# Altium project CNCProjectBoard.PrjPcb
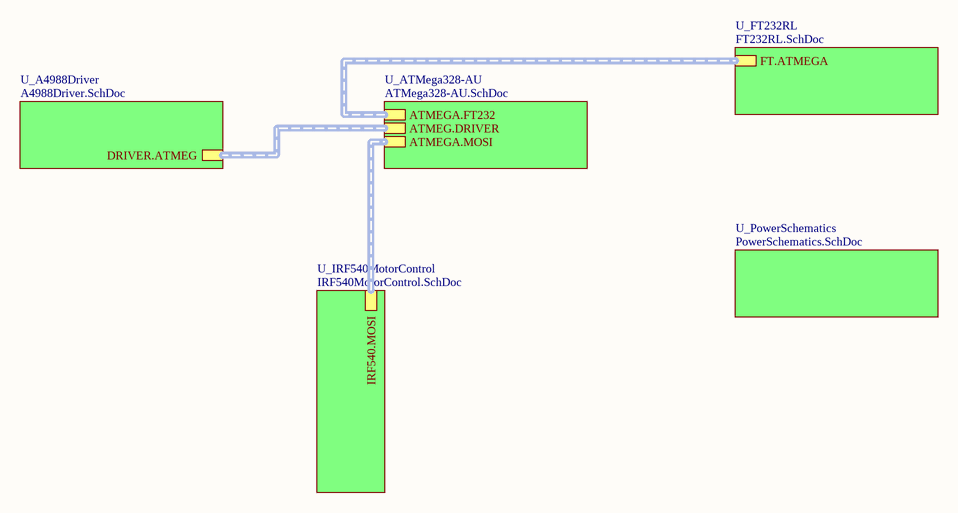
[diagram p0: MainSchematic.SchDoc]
6 sheets, 89 parts. Net scope: hierarchical (ports join the sheet entries above them; power ports are global).
Board file: PCB1.PcbDoc
Sheets:
  MainSchematic.SchDoc
    U_A4988Driver = A4988Driver.SchDoc
    U_ATMega328-AU = ATMega328-AU.SchDoc
    U_FT232RL = FT232RL.SchDoc
    U_IRF540MotorControl = IRF540MotorControl.SchDoc
    U_PowerSchematics = PowerSchematics.SchDoc

## Sheet MainSchematic.SchDoc
size A; SheetNumber: 1; SheetTotal: 6

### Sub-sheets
U_A4988Driver = A4988Driver.SchDoc: DRIVER.ATMEG (harness DRIVER-ATMEGA)
U_ATMega328-AU = ATMega328-AU.SchDoc: ATMEGA.FT232 (harness FT-ATMega), ATMEG.DRIVER (harness DRIVER-ATMEGA), ATMEGA.MOSI (harness IRF540-ATMEGA)
U_FT232RL = FT232RL.SchDoc: FT.ATMEGA (harness FT-ATMega)
U_IRF540MotorControl = IRF540MotorControl.SchDoc: IRF540.MOSI (harness IRF540-ATMEGA)
U_PowerSchematics = PowerSchematics.SchDoc: no entries

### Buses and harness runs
harness sheet U_A4988Driver/DRIVER.ATMEG = sheet U_ATMega328-AU/ATMEG.DRIVER
harness sheet U_ATMega328-AU/ATMEGA.FT232 = sheet U_FT232RL/FT.ATMEGA
harness sheet U_ATMega328-AU/ATMEGA.MOSI = sheet U_IRF540MotorControl/IRF540.MOSI

## Sheet A4988Driver.SchDoc
size A4; SheetNumber: 2; SheetTotal: 6
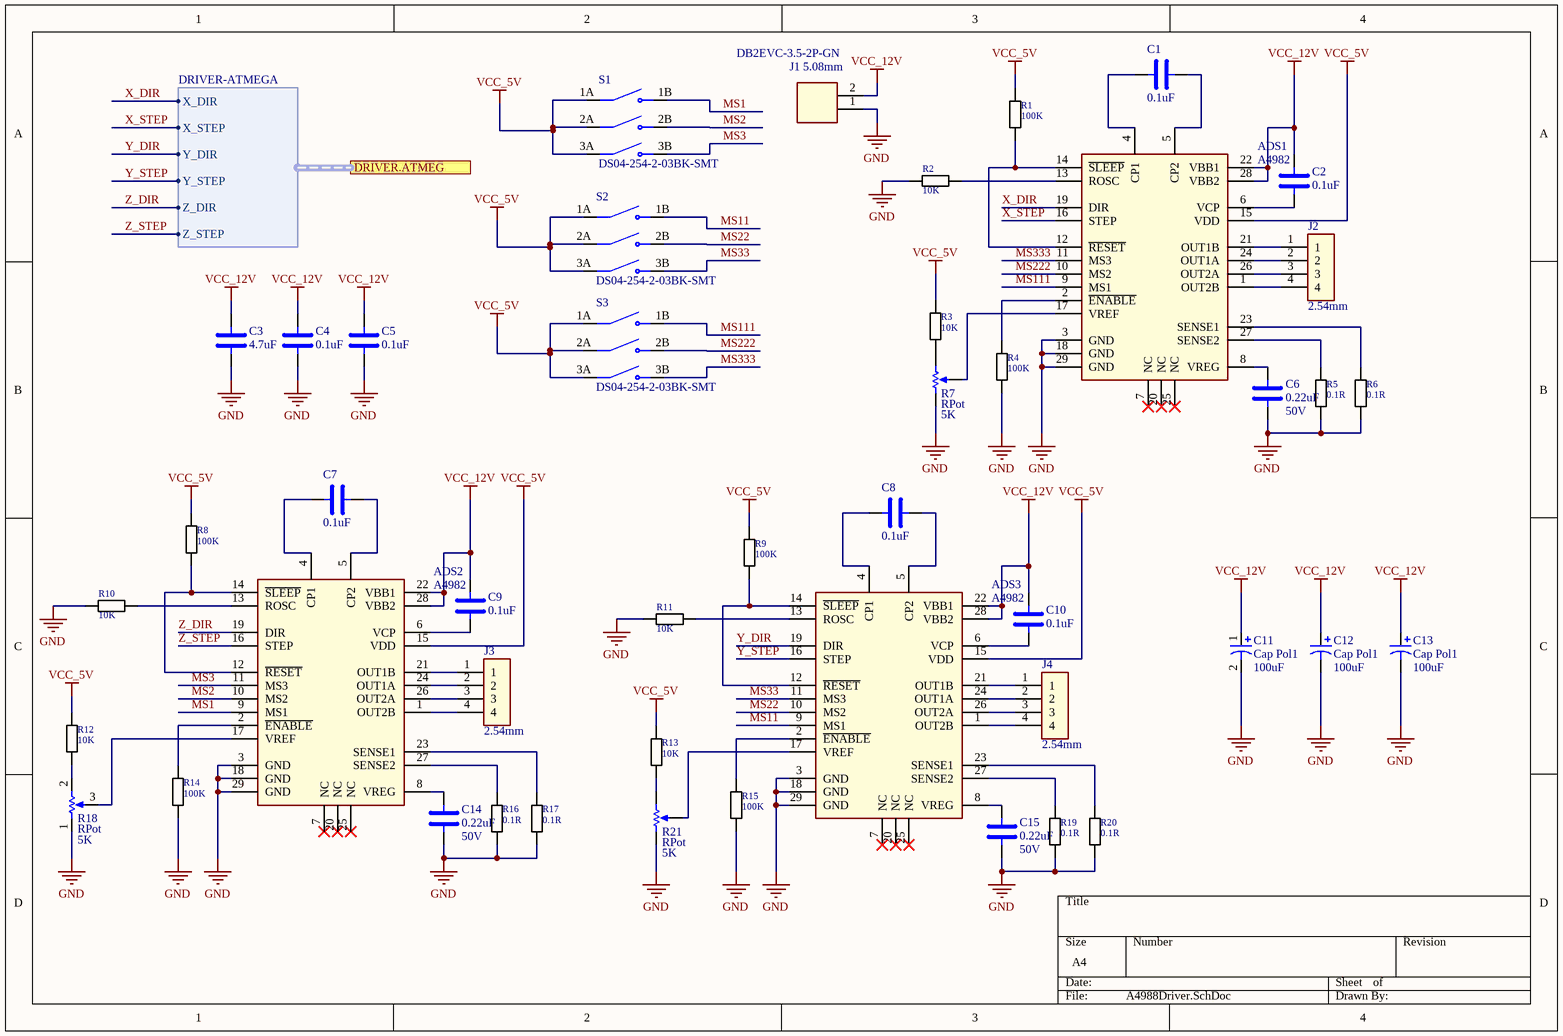
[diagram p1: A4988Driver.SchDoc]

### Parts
ADS1  A4982  [QFN50P500X500X90-29N]
ADS2  A4982  [QFN50P500X500X90-29N]
ADS3  A4982  [QFN50P500X500X90-29N]
C1  0.1uF  [CAPC2012X140N]
C2  0.1uF  [CAPC2012X140N]
C3  4.7uF  [CAPC2012X140N]
C4  0.1uF  [CAPC2012X140N]
C5  0.1uF  [CAPC2012X140N]
C6  0.22uF  Voltage: 50V  [CAPC2012X140N]
C7  0.1uF  [CAPC2012X140N]
C8  0.1uF  [CAPC2012X140N]
C9  0.1uF  [CAPC2012X140N]
C10  0.1uF  [CAPC2012X140N]
C11  Cap Pol1  value 100uF  [CAPPRD250W50D630H1500]
C12  Cap Pol1  value 100uF  [CAPPRD250W50D630H1500]
C13  Cap Pol1  value 100uF  [CAPPRD250W50D630H1500]
C14  0.22uF  Voltage: 50V  [CAPC2012X140N]
C15  0.22uF  Voltage: 50V  [CAPC2012X140N]
J1  DB2EVC-3.5-2P-GN  Pitch: 5.08mm  [5MM_2POS_TERM_BLOCK]
J2  2.54mm  [HEADER1X4]
J3  2.54mm  [HEADER1X4]
J4  2.54mm  [HEADER1X4]
R1  100K  [RESC2012X60N]
R2  10K  [RESC2012X60N]
R3  10K  [RESC2012X60N]
R4  100K  [RESC2012X60N]
R5  0.1R  [RESAD1100W55L680D260]
R6  0.1R  [RESAD1100W55L680D260]
R7  RPot  value 5K  [PT10RV10103A2020PMS]
R8  100K  [RESC2012X60N]
R9  100K  [RESC2012X60N]
R10  10K  [RESC2012X60N]
R11  10K  [RESC2012X60N]
R12  10K  [RESC2012X60N]
R13  10K  [RESC2012X60N]
R14  100K  [RESC2012X60N]
R15  100K  [RESC2012X60N]
R16  0.1R  [RESAD1100W55L680D260]
R17  0.1R  [RESAD1100W55L680D260]
R18  RPot  value 5K  [PT10RV10103A2020PMS]
R19  0.1R  [RESAD1100W55L680D260]
R20  0.1R  [RESAD1100W55L680D260]
R21  RPot  value 5K  [PT10RV10103A2020PMS]
S1  DS04-254-2-03BK-SMT  [SW_DS01-254-S-03BE]
S2  DS04-254-2-03BK-SMT  [SW_DS01-254-S-03BE]
S3  DS04-254-2-03BK-SMT  [SW_DS01-254-S-03BE]

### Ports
DRIVER.ATMEG (harness DRIVER-ATMEGA)

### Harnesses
DRIVER-ATMEGA: X_DIR, X_STEP, Y_DIR, Y_STEP, Z_DIR, Z_STEP

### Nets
GND: ADS1.3(GND) ADS1.18(GND) ADS1.29(GND) ADS2.3(GND) ADS2.18(GND) ADS2.29(GND) ADS3.3(GND) ADS3.18(GND) ADS3.29(GND) C3.1 C4.1 C5.1 C6.1 C11.2 C12.2 C13.2 C14.1 C15.1 J1.1 R2.1 R4.1 R5.1 R6.1 R7.1(TOP) R10.1 R11.1 R14.1 R15.1 R16.1 R17.1 R18.1(TOP) R19.1 R20.1 R21.1(TOP)
VCC_5V: ADS1.15(VDD) ADS2.15(VDD) ADS3.15(VDD) R1.2 R3.2 R8.2 R9.2 R12.2 R13.2 S1.1A(COM1) S1.2A(COM2) S1.3A(COM3) S2.1A(COM1) S2.2A(COM2) S2.3A(COM3) S3.1A(COM1) S3.2A(COM2) S3.3A(COM3)
VCC_12V: ADS1.22(VBB1) ADS1.28(VBB2) ADS2.22(VBB1) ADS2.28(VBB2) ADS3.22(VBB1) ADS3.28(VBB2) C2.2 C3.2 C4.2 C5.2 C9.2 C10.2 C11.1 C12.1 C13.1 J1.2
MS1: ADS2.9(MS1) S1.1B(NO1)
MS2: ADS2.10(MS2) S1.2B(NO2)
MS3: ADS2.11(MS3) S1.3B(NO3)
MS11: ADS3.9(MS1) S2.1B(NO1)
MS22: ADS3.10(MS2) S2.2B(NO2)
MS33: ADS3.11(MS3) S2.3B(NO3)
MS111: ADS1.9(MS1) S3.1B(NO1)
MS222: ADS1.10(MS2) S3.2B(NO2)
MS333: ADS1.11(MS3) S3.3B(NO3)
X_DIR: ADS1.19(DIR) ; port DRIVER.ATMEG.X_DIR
X_STEP: ADS1.16(STEP) ; port DRIVER.ATMEG.X_STEP
Y_DIR: ADS3.19(DIR) ; port DRIVER.ATMEG.Y_DIR
Y_STEP: ADS3.16(STEP) ; port DRIVER.ATMEG.Y_STEP
Z_DIR: ADS2.19(DIR) ; port DRIVER.ATMEG.Z_DIR
Z_STEP: ADS2.16(STEP) ; port DRIVER.ATMEG.Z_STEP
NetADS1_1: ADS1.1(OUT2B) J2.4
NetADS1_2: ADS1.2(~{ENABLE}) R4.2
NetADS1_4: ADS1.4(CP1) C1.2
NetADS1_5: ADS1.5(CP2) C1.1
NetADS1_6: ADS1.6(VCP) C2.1
NetADS1_8: ADS1.8(VREG) C6.2
NetADS1_12: ADS1.12(~{RESET}) ADS1.14(~{SLEEP}) R1.1
NetADS1_13: ADS1.13(ROSC) R2.2
NetADS1_17: ADS1.17(VREF) R7.3(TAP)
NetADS1_21: ADS1.21(OUT1B) J2.1
NetADS1_23: ADS1.23(SENSE1) R6.2
NetADS1_24: ADS1.24(OUT1A) J2.2
NetADS1_26: ADS1.26(OUT2A) J2.3
NetADS1_27: ADS1.27(SENSE2) R5.2
NetADS2_1: ADS2.1(OUT2B) J3.4
NetADS2_2: ADS2.2(~{ENABLE}) R14.2
NetADS2_4: ADS2.4(CP1) C7.2
NetADS2_5: ADS2.5(CP2) C7.1
NetADS2_6: ADS2.6(VCP) C9.1
NetADS2_8: ADS2.8(VREG) C14.2
NetADS2_12: ADS2.12(~{RESET}) ADS2.14(~{SLEEP}) R8.1
NetADS2_13: ADS2.13(ROSC) R10.2
NetADS2_17: ADS2.17(VREF) R18.3(TAP)
NetADS2_21: ADS2.21(OUT1B) J3.1
NetADS2_23: ADS2.23(SENSE1) R17.2
NetADS2_24: ADS2.24(OUT1A) J3.2
NetADS2_26: ADS2.26(OUT2A) J3.3
NetADS2_27: ADS2.27(SENSE2) R16.2
NetADS3_1: ADS3.1(OUT2B) J4.4
NetADS3_2: ADS3.2(~{ENABLE}) R15.2
NetADS3_4: ADS3.4(CP1) C8.2
NetADS3_5: ADS3.5(CP2) C8.1
NetADS3_6: ADS3.6(VCP) C10.1
NetADS3_8: ADS3.8(VREG) C15.2
NetADS3_12: ADS3.12(~{RESET}) ADS3.14(~{SLEEP}) R9.1
NetADS3_13: ADS3.13(ROSC) R11.2
NetADS3_17: ADS3.17(VREF) R21.3(TAP)
NetADS3_21: ADS3.21(OUT1B) J4.1
NetADS3_23: ADS3.23(SENSE1) R20.2
NetADS3_24: ADS3.24(OUT1A) J4.2
NetADS3_26: ADS3.26(OUT2A) J4.3
NetADS3_27: ADS3.27(SENSE2) R19.2
NetR3_1: R3.1 R7.2(BOT)
NetR12_1: R12.1 R18.2(BOT)
NetR13_1: R13.1 R21.2(BOT)

Not connected (* = marked no-connect by the designer): ADS1 7(NC)* 20(NC)* 25(NC)*; ADS2 7(NC)* 20(NC)* 25(NC)*; ADS3 7(NC)* 20(NC)* 25(NC)*

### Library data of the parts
C1 C2 C4 C5 C7-C10 = CAP CER 0.1uF
C3 = CAP CER 4.7uF
C6 C14 C15 = CAP CER 0.22uF 0603 50VDC 10% X5R: Manufacturer: YAGEO; Manufacturer Part Number: CC0603JRNPO9BN180
C11-C13 = Cap Pol1: Polarized Capacitor (Radial)
J1 = TERM_BLOCK_2PIN_VERT_3.5MM: 300V 8A 2 Straight pin -40℃~+105℃ 1 3.5mm Green Board Edge/Receptacle-Close Plugin,P=3.5mm Pluggable System Terminal Block ROHS; Manufacturer: DIBO; Number of Positions: 2
J2-J4 = Header_1x4: Male Header 1x4; Manufacturer: Ckmtw(Shenzhen Cankemeng); Manufacturer Part Number: B-2100S04P-A110; Number of Positions: 4
R1 R4 R8 R9 R14 R15 = RES 100K 0603 100mW 0.1%: Manufacturer: YAGEO; Manufacturer Part Number: RT0603BRD07100KL
R2 R10 R11 = RES 10K 0603 100mW 0.1%: Manufacturer: YAGEO; Manufacturer Part Number: RT0603BRE0710KL
R3 R12 R13 = RES 10K 0805 125mW 1%: Manufacturer: UNI-ROYAL(Uniroyal Elec); Manufacturer Part Number: 0805W8F1002T5E
R5 R6 R16 R17 R19 R20 = RES 0.1R TH
R7 R18 R21 = RPot: Potentiometer; Sim Note: Enter the Resistance value and the set point into parameter fields.; Set Position: 0.5
S1-S3 = DS04-254-2-03BK-SMT: DS05-127-2-04BK-SMT-TR; MF: {'manufacturer': u'CUI'}

## Sheet ATMega328-AU.SchDoc
size A4; SheetNumber: 3; SheetTotal: 6
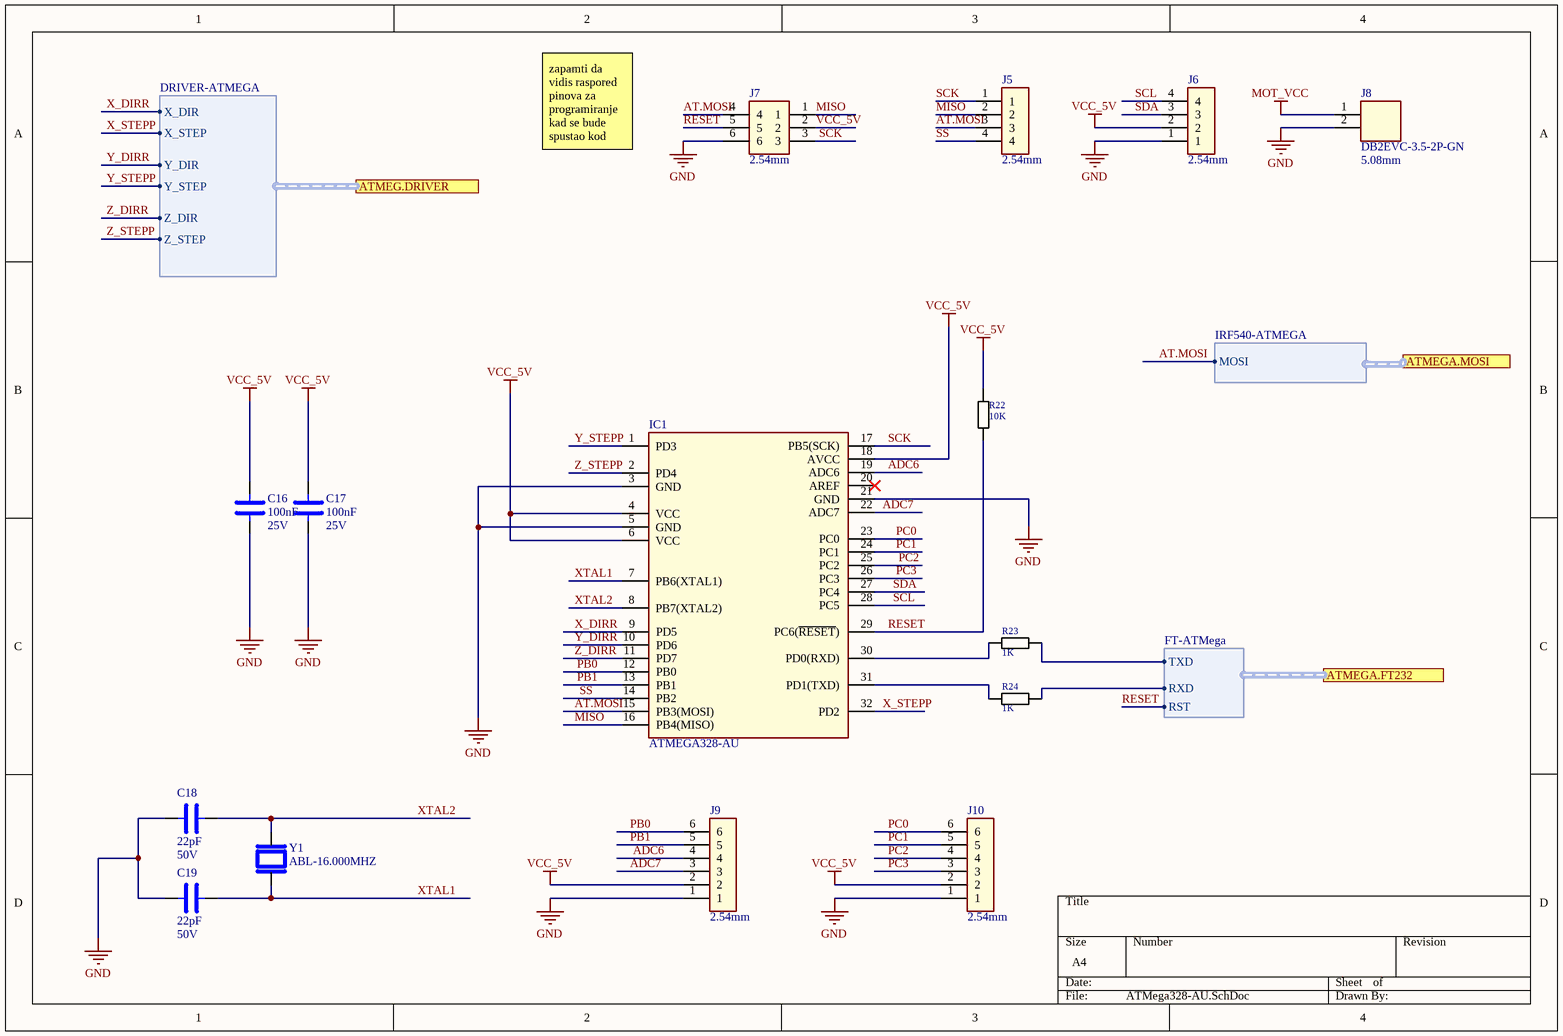
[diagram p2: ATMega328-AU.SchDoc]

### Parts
C16  100nF  Voltage: 25V  [CAPC2012X140N]
C17  100nF  Voltage: 25V  [CAPC2012X140N]
C18  22pF  Voltage: 50V  [CAPC2012X140N]
C19  22pF  Voltage: 50V  [CAPC2012X140N]
IC1  ATMEGA328-AU  [QFP80P900X900X120-32N]
J5  2.54mm  [HEADER1X4]
J6  2.54mm  [HEADER1X4]
J7  2.54mm  [TE_5-146257-3]
J8  DB2EVC-3.5-2P-GN  Pitch: 5.08mm  [5MM_2POS_TERM_BLOCK]
J9  2.54mm  [HEADER1X6]
J10  2.54mm  [HEADER1X6]
R22  10K  [RESC2012X60N]
R23  1K  [RESC2012X60N]
R24  1K  [RESC2012X60N]
Y1  ABL-16.000MHZ  [XTAL_ECS-30-S-1X]

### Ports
ATMEG.DRIVER (harness DRIVER-ATMEGA), ATMEGA.FT232 (harness FT-ATMega), ATMEGA.MOSI (harness IRF540-ATMEGA)

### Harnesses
FT-ATMega: TXD, RXD, RST
DRIVER-ATMEGA: X_DIR, Y_DIR, Z_STEP, X_STEP, Z_DIR, Y_STEP
IRF540-ATMEGA: MOSI

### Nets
GND: C16.1 C17.1 C18.2 C19.2 IC1.3(GND) IC1.5(GND) IC1.21(GND) J6.1 J7.6 J8.2 J9.1 J10.1
MOT_VCC: J8.1
VCC_5V: C16.2 C17.2 IC1.4(VCC) IC1.6(VCC) IC1.18(AVCC) J6.2 J7.2 J9.2 J10.2 R22.2
ADC6: IC1.19(ADC6) J9.4
ADC7: IC1.22(ADC7) J9.3
AT.MOSI: IC1.15(PB3(MOSI)) J5.3 J7.4 ; port ATMEGA.MOSI.MOSI
MISO: IC1.16(PB4(MISO)) J5.2 J7.1
PB0: IC1.12(PB0) J9.6
PB1: IC1.13(PB1) J9.5
PC0: IC1.23(PC0) J10.6
PC1: IC1.24(PC1) J10.5
PC2: IC1.25(PC2) J10.4
PC3: IC1.26(PC3) J10.3
RESET: IC1.29(PC6(~{RESET})) J7.5 R22.1 ; port ATMEGA.FT232.RST
RXD: R24.2 ; port ATMEGA.FT232.RXD
SCK: IC1.17(PB5(SCK)) J5.1 J7.3
SCL: IC1.28(PC5) J6.4
SDA: IC1.27(PC4) J6.3
SS: IC1.14(PB2) J5.4
TXD: R23.2 ; port ATMEGA.FT232.TXD
X_DIRR: IC1.9(PD5) ; port ATMEG.DRIVER.X_DIR  [project net X_DIR]
X_STEPP: IC1.32(PD2) ; port ATMEG.DRIVER.X_STEP  [project net X_STEP]
XTAL1: C19.1 IC1.7(PB6(XTAL1)) Y1.1
XTAL2: C18.1 IC1.8(PB7(XTAL2)) Y1.2
Y_DIRR: IC1.10(PD6) ; port ATMEG.DRIVER.Y_DIR  [project net Y_DIR]
Y_STEPP: IC1.1(PD3) ; port ATMEG.DRIVER.Y_STEP  [project net Y_STEP]
Z_DIRR: IC1.11(PD7) ; port ATMEG.DRIVER.Z_DIR  [project net Z_DIR]
Z_STEPP: IC1.2(PD4) ; port ATMEG.DRIVER.Z_STEP  [project net Z_STEP]
NetIC1_30: IC1.30(PD0(RXD)) R23.1
NetIC1_31: IC1.31(PD1(TXD)) R24.1

Not connected (* = marked no-connect by the designer): IC1 20(AREF)*

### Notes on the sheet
- zapamti da vidis raspored pinova za programiranje kad se bude spustao kod

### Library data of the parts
C16 C17 = CAP CER 100nF 0603 25VDC 10% X7R: Manufacturer: Samsung Electro-Mechanics; Manufacturer Part Number: CL10B104KA8NNNC
C18 C19 = CAP CER 22pF 0805 50VDC 10% X5R: Manufacturer: Samsung Electro-Mechanics; Manufacturer Part Number: CL10A106KP8NNNC
J5 J6 = Header_1x4: as J2 on sheet A4988Driver
J7 = Header_2x3: Male Header 2x3
J8 = TERM_BLOCK_2PIN_VERT_3.5MM: as J1 on sheet A4988Driver
J9 J10 = Header_1x6: Female Header 1x6; Manufacturer: MOLEX; Manufacturer Part Number: 0901471106; Number of Positions: 6
R22 = RES 10K 0603 100mW 0.1%: as R2 on sheet A4988Driver
R23 R24 = RES 1K 0603 250mW 5%: RES 100K 0603 250mW 5%; Manufacturer: Panasonic; Manufacturer Part Number: ERJ-PA3J102V
Y1 = ABL-16.000MHZ: 16 MHz Â±10ppm Crystal 18pF 40 Ohms HC-49/US; MF: Abracon Corporation

## Sheet FT232RL.SchDoc
size A4; SheetNumber: 5; SheetTotal: 6
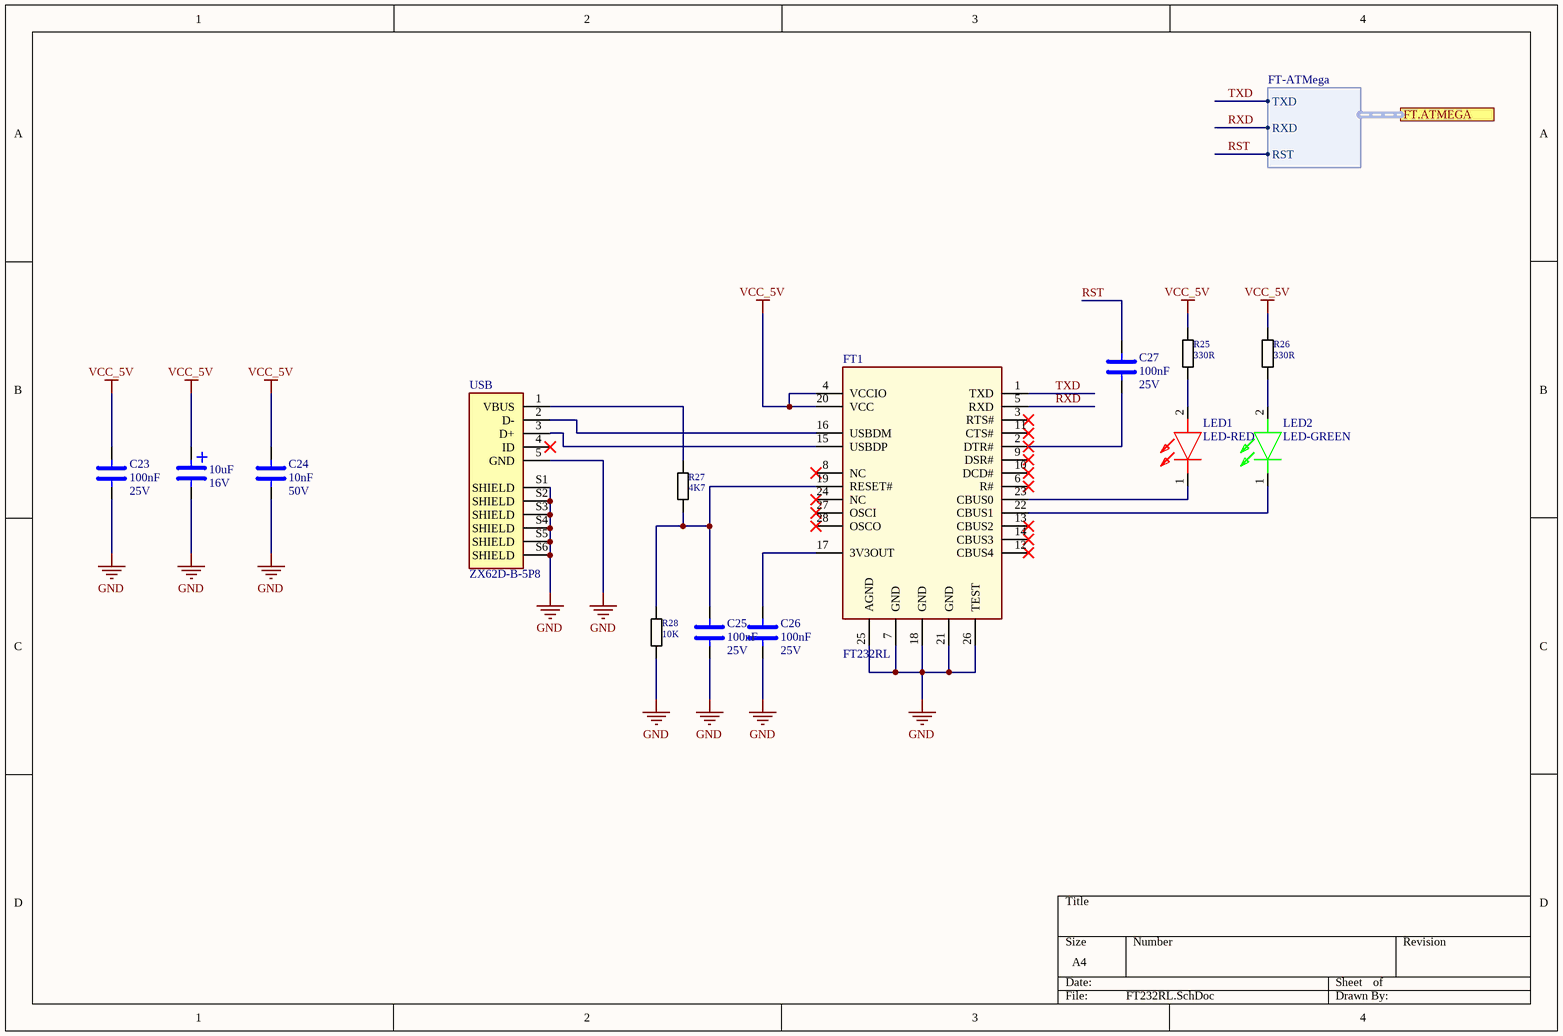
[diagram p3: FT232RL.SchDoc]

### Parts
C22  10uF  Voltage: 16V  [CAP_EEE1CA101WAP]
C23  100nF  Voltage: 25V  [CAPC2012X140N]
C24  10nF  Voltage: 50V  [CAPC2012X140N]
C25  100nF  Voltage: 25V  [CAPC2012X140N]
C26  100nF  Voltage: 25V  [CAPC2012X140N]
C27  100nF  Voltage: 25V  [CAPC2012X140N]
FT1  FT232RL  [SSOP28-0.65-10.2X5.2MM]
LED1  LED-RED  [LEDM168X65N_RED]
LED2  LED-GREEN  [LEDM168X65N_GREEN]
R25  330R  [RESC2012X60N]
R26  330R  [RESC2012X60N]
R27  4K7  [RESC2012X60N]
R28  10K  [RESC2012X60N]
USB  ZX62D-B-5P8  [HRS_ZX62D-B-5P8]

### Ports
FT.ATMEGA (harness FT-ATMega)

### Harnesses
FT-ATMega: TXD, RXD, RST

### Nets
GND: C22.2 C23.1 C24.1 C25.1 C26.1 FT1.7(GND) FT1.18(GND) FT1.21(GND) FT1.25(AGND) FT1.26(TEST) R28.1 USB.5(GND) USB.S1(SHIELD) USB.S2(SHIELD) USB.S3(SHIELD) USB.S4(SHIELD) USB.S5(SHIELD) USB.S6(SHIELD)
VCC_5V: C22.1 C23.2 C24.2 FT1.4(VCCIO) FT1.20(VCC) R25.2 R26.2
RST: C27.2 ; port FT.ATMEGA.RST  [project net RESET]
RXD: FT1.5(RXD) ; port FT.ATMEGA.RXD
TXD: FT1.1(TXD) ; port FT.ATMEGA.TXD
NetC25_2: C25.2 FT1.19(RESET#) R27.1 R28.2
NetC26_2: C26.2 FT1.17(3V3OUT)
NetC27_1: C27.1 FT1.2(DTR#)
NetFT1_15: FT1.15(USBDP) USB.3(D+)
NetFT1_16: FT1.16(USBDM) USB.2(D-)
NetFT1_22: FT1.22(CBUS1) LED2.1(K)
NetFT1_23: FT1.23(CBUS0) LED1.1
NetLED1_2: LED1.2 R25.1
NetLED2_2: LED2.2(A) R26.1
NetR27_2: R27.2 USB.1(VBUS)

Not connected (* = marked no-connect by the designer): FT1 3(RTS#)* 6(R#)* 8(NC)* 9(DSR#)* 10(DCD#)* 11(CTS#)* 12(CBUS4)* 13(CBUS2)* 14(CBUS3)* 24(NC)* 27(OSCI)* 28(OSCO)*; USB 4(ID)*

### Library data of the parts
C22 = CAP CER 10uF 1206 25VDC 10% TANTAL: CAP CER 10uF 1206 16VDC 10% TANTAL; Manufacturer: Kyocera AVX; Manufacturer Part Number: TAJA106K016RNJ; Dielectric: Tantalum
C23 C25-C27 = CAP CER 100nF 0603 25VDC 10% X7R: as C16 on sheet ATMega328-AU
C24 = CAP CER 10nF 0603 50VDC 10% X7R: Manufacturer: YAGEO; Manufacturer Part Number: CC0603KRX7R9BB103
FT1 = FT232RL: USB Interface IC USB to Serial UART Enhanced IC SSOP-28
LED1 = LED_RED: 5mA 632nm Colorless transparence -40℃~+85℃ 617.5nm~633.5nm Red 120° 60mW 0603 Light Emitting Diodes (LED) ROHS; Manufacturer: Everlight Elec; Manufacturer Part Number: 19-217/R6C-AL1M2VY/3T
LED2 = LED_GREEN: 20mA 518nm Colorless transparence -40℃~+85℃ 520nm~535nm Emerald 120° 110mW 0603 Light Emitting Diodes (LED) ROHS; Manufacturer: Everlight Elec; Manufacturer Part Number: 19-217/GHC-YR1S2/3T; Colour: Brilliant Green
R25 R26 = RES 330R 0603 100mW 5%: Manufacturer: Panasonic; Manufacturer Part Number: ERJ-3GEYJ331V
R27 = RES 4K7 0805 125mW 1%: Manufacturer: UNI-ROYAL(Uniroyal Elec); Manufacturer Part Number: 0805W8F4701T5E
R28 = RES 10K 0603 100mW 0.1%: as R2 on sheet A4988Driver
USB = ZX62D-B-5P8: USB - micro B USB 2.0 Receptacle Connector 5 Position Surface Mount, Right Angle; Through Hole; MF: Hirose Connector

## Sheet IRF540MotorControl.SchDoc
size A4; SheetNumber: 6; SheetTotal: 6
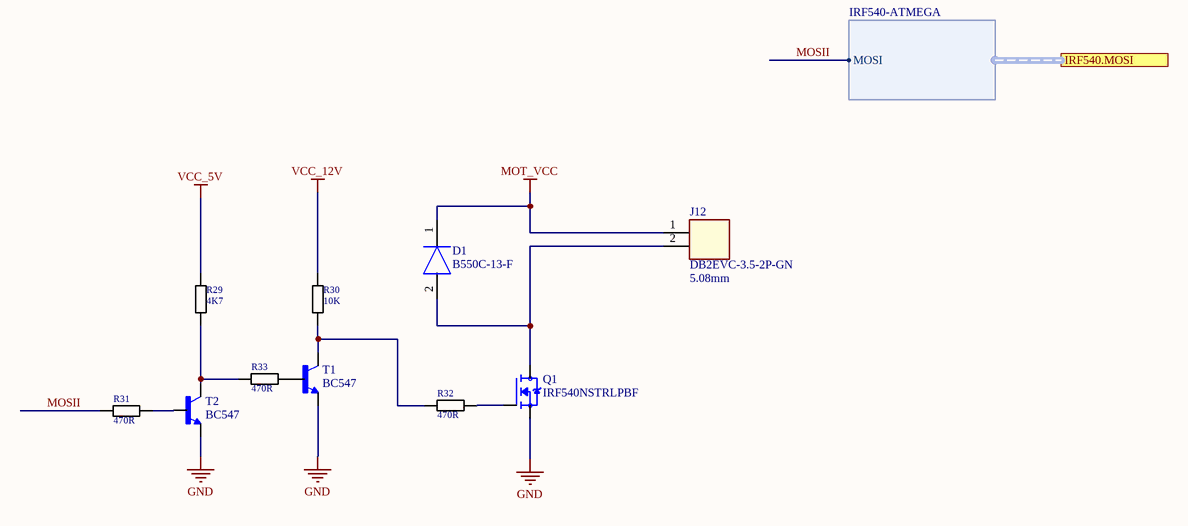
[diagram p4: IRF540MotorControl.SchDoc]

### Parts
D1  B550C-13-F  [DIOAD1950W125L950D560]
J12  DB2EVC-3.5-2P-GN  Pitch: 5.08mm  [5MM_2POS_TERM_BLOCK]
Q1  IRF540NSTRLPBF  [TO254P1052X465X1989-3]
R29  4K7  [RESC2012X60N]
R30  10K  [RESC2012X60N]
R31  470R  [RESC2012X60N]
R32  470R  [RESC2012X60N]
R33  470R  [RESC2012X60N]
T1  BC547  [TO92250P510H770-3]
T2  BC547  [TO92250P510H770-3]

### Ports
IRF540.MOSI (harness IRF540-ATMEGA)

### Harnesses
IRF540-ATMEGA: MOSI

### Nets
GND: Q1.3 T1.E T2.E
MOT_VCC: D1.1 J12.1
VCC_5V: R29.2
VCC_12V: R30.2
MOSII: R31.1 ; port IRF540.MOSI.MOSI  [project net AT.MOSI]
NetD1_2: D1.2 J12.2 Q1.2
NetQ1_1: Q1.1 R32.2
NetR29_1: R29.1 R33.1 T2.C
NetR30_1: R30.1 R32.1 T1.C
NetR31_2: R31.2 T2.B
NetR33_2: R33.2 T1.B

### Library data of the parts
D1 = B550C-13-F: Schottky Diodes & Rectifiers 50V 5A; Manufacturer: Diodes Inc.; Vf - Forward Voltage: 575mV
J12 = TERM_BLOCK_2PIN_VERT_3.5MM: as J1 on sheet A4988Driver
Q1 = IRF540NSTRLPBF: MOSFET, Power; N-Ch; VDSS 100V; RDS(ON) 44Milliohms; ID 33A; D2Pak; PD 130W; VGS +/-20; MF: Infineon Technologies
R29 = RES 5K1 0805 125mW 1%: Manufacturer: UNI-ROYAL(Uniroyal Elec); Manufacturer Part Number: 0805W8F4701T5E
R30 = RES 10K 0805 125mW 1%: as R3 on sheet A4988Driver
R31-R33 = RES 470R 0603 250mW 1%: Manufacturer: YAGEO; Manufacturer Part Number: ESR03EZPF4700
T1 T2 = BC547: Trans GP BJT NPN 45V 0.1A 500mW 3-Pin TO-92 T/R; MF: ON Semiconductor

## Sheet PowerSchematics.SchDoc
size A4; SheetNumber: 4; SheetTotal: 6
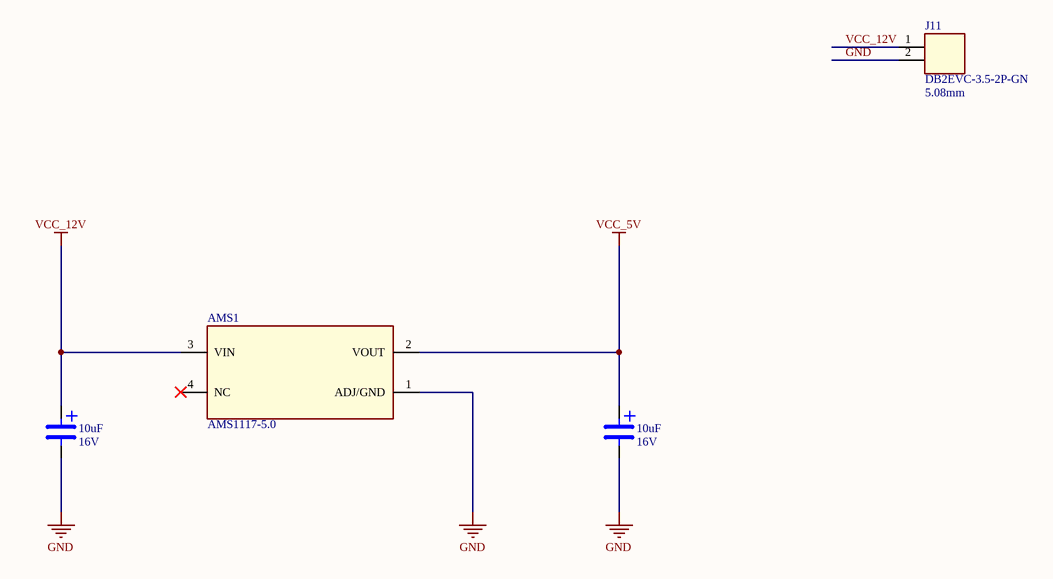
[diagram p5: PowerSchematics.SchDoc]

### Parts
AMS1  AMS1117-5.0  [SOT229P700X180-4N]
C20  10uF  Voltage: 16V  [CAP_EEE1CA101WAP]
C21  10uF  Voltage: 16V  [CAP_EEE1CA101WAP]
J11  DB2EVC-3.5-2P-GN  Pitch: 5.08mm  [5MM_2POS_TERM_BLOCK]

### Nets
GND: AMS1.1(ADJ/GND) C20.2 C21.2 J11.2
VCC_5V: AMS1.2(VOUT) C21.1
VCC_12V: AMS1.3(VIN) C20.1 J11.1

Not connected (* = marked no-connect by the designer): AMS1 4(NC)*

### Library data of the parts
C20 C21 = CAP CER 10uF 1206 25VDC 10% TANTAL: as C22 on sheet FT232RL
J11 = TERM_BLOCK_2PIN_VERT_3.5MM: as J1 on sheet A4988Driver

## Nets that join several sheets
GND: A4988Driver (34 pins), ATMega328-AU (12 pins), FT232RL (18 pins), IRF540MotorControl (Q1.3 T1.E T2.E), PowerSchematics (AMS1.1 C20.2 C21.2 J11.2)
MOT_VCC: ATMega328-AU (J8.1), IRF540MotorControl (D1.1 J12.1)
VCC_5V: A4988Driver (18 pins), ATMega328-AU (10 pins), FT232RL (7 pins), IRF540MotorControl (R29.2), PowerSchematics (AMS1.2 C21.1)
VCC_12V: A4988Driver (16 pins), IRF540MotorControl (R30.2), PowerSchematics (AMS1.3 C20.1 J11.1)
AT.MOSI: ATMega328-AU (IC1.15 J5.3 J7.4), IRF540MotorControl (R31.1)
RESET: ATMega328-AU (IC1.29 J7.5 R22.1), FT232RL (C27.2)
RXD: ATMega328-AU (R24.2), FT232RL (FT1.5)
TXD: ATMega328-AU (R23.2), FT232RL (FT1.1)
X_DIR: A4988Driver (ADS1.19), ATMega328-AU (IC1.9)
X_STEP: A4988Driver (ADS1.16), ATMega328-AU (IC1.32)
Y_DIR: A4988Driver (ADS3.19), ATMega328-AU (IC1.10)
Y_STEP: A4988Driver (ADS3.16), ATMega328-AU (IC1.1)
Z_DIR: A4988Driver (ADS2.19), ATMega328-AU (IC1.11)
Z_STEP: A4988Driver (ADS2.16), ATMega328-AU (IC1.2)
